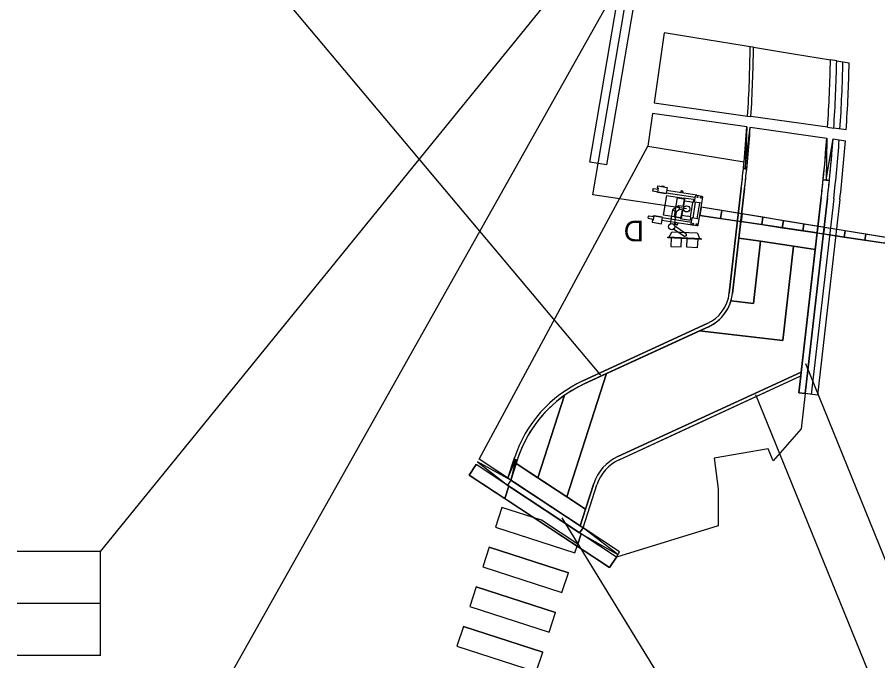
# Model space of a CAD drawing. Extents: x -728547 to -728179, y -1073068 to -1072839.
# Drawn here: x -728529.45 to -728508.81, y -1073057.23 to -1073041.79 of the extents above; entities that cross this region are included whole.
import ezdxf

# ---------------------------------------------------------------- set-up
doc = ezdxf.new("R2010")
doc.units = 0
for name, color, linetype in [('_NOR-návrh tenká', 7, 'Continuous'), ('_NOR-popis', 7, 'Continuous'), ('_NOR-VDZ', 7, 'Continuous'), ('_NOR-šraf_+-0', 7, 'Continuous'), ('_NOR-šraf_+12', 7, 'Continuous'), ('_NOR-šraf_+6', 7, 'Continuous'), ('_NOR-šraf_bezbariéra', 7, 'Continuous'), ('_NOR-šraf_chodník', 7, 'Continuous'), ('_NOR-šraf_signální pás', 7, 'Continuous'), ('_NOR-šraf_varovný pás', 7, 'Continuous'), ('_NOR-šraf_vozovka', 7, 'Continuous'), ('_NOR-šraf_zeleň', 7, 'Continuous'), ('KOS_kabelová trasa', 7, 'Continuous'), ('KOS_kabelová trasa popis', 7, 'Continuous'), ('KOS_nové prvky PZZ', 7, 'Continuous')]:
    doc.layers.add(name, color=color, linetype=linetype)

# ---------------------------------------------------------------- blocks, each defined once
blk = doc.blocks.new('Závora D')
for p, q in [((-0.7, 0.501), (-0.705, 0.472)), ((-0.599, 0.542), (-0.6, 0.536)), ((-0.539, 0.532), (-0.599, 0.542)), ((0.242, 0.325), (-0.48, 0.437)), ((0.207, 0.27), (-0.489, 0.378)), ((-0.291, -0.184), (-0.22, 0.276)), ((0.19, 0.161), (0.213, 0.305)), ((0.242, 0.325), (0.213, 0.305)), ((0.281, -0.391), (0.385, 0.279)), ((0.363, 0.306), (0.385, 0.279)), ((-0.193, 0.076), (-0.17, -0.019)), ((0.095, -0.191), (0.149, 0.155)), ((0.155, -0.223), (0.214, 0.157)), ((0.363, 0.134), (0.19, 0.161)), ((0.254, -0.239), (0.314, 0.142)), ((0.349, 0.043), (0.318, -0.155)), ((0.349, 0.043), (0.318, -0.155)), ((0.349, 0.043), (0.318, -0.155)), ((0.349, 0.043), (0.318, -0.155)), ((6.764, -1.002), (0.349, 0.043)), ((-0.337, -0.025), (-0.253, -0.076)), ((6.748, -1.108), (0.318, -0.155)), ((-0.821, -0.272), (-0.816, -0.244)), ((-0.737, -0.342), (-0.736, -0.336)), ((-0.676, -0.352), (-0.737, -0.342)), ((0.131, -0.391), (-0.591, -0.279)), ((0.114, -0.328), (-0.582, -0.22)), ((0.131, -0.391), (0.109, -0.364)), ((0.304, -0.246), (0.131, -0.219)), ((0.252, -0.41), (0.131, -0.391)), ((0.252, -0.41), (0.281, -0.391)), ((-0.069, -0.656), (-0.314, -0.489)), ((0.347, -0.72), (-0.449, -0.683)), ((6.764, -1.002), (6.748, -1.108))]:
    blk.add_line(p, q)
for points in [[(-0.807, 0.488), (-0.815, 0.434), (-0.81, 0.427), (-0.692, 0.409)], [(-0.807, 0.488), (-0.683, 0.469)], [(-0.468, 0.515), (-0.491, 0.368), (-0.694, 0.4), (-0.679, 0.497), (-0.7, 0.501), (-0.693, 0.55), (-0.468, 0.515)], [(-0.58, 0.533), (-0.54, 0.526)], [(-0.539, 0.532), (-0.54, 0.526)], [(-0.114, 0.432), (-0.127, 0.434), (-0.129, 0.428), (-0.133, 0.429), (-0.135, 0.419), (-0.138, 0.419), (-0.142, 0.396), (-0.15, 0.398), (-0.151, 0.392), (-0.152, 0.386)], [(-0.114, 0.432), (-0.101, 0.43), (-0.101, 0.423), (-0.096, 0.423), (-0.098, 0.413), (-0.094, 0.412), (-0.098, 0.389), (-0.089, 0.388), (-0.09, 0.382), (-0.091, 0.377)], [(-0.694, 0.4), (-0.716, 0.403), (-0.715, 0.412)], [(-0.494, 0.369), (-0.495, 0.361), (-0.693, 0.392), (-0.692, 0.399)], [(-0.298, -0.194), (-0.551, -0.155), (-0.477, 0.316), (-0.225, 0.277)], [(-0.225, 0.277), (-0.298, -0.194)], [(-0.221, 0.265), (-0.074, 0.242), (-0.07, 0.24), (-0.066, 0.236), (-0.063, 0.231), (-0.063, 0.226), (-0.089, 0.059)], [(-0.22, 0.276), (-0.07, 0.253), (-0.061, 0.249), (-0.055, 0.242), (-0.05, 0.235), (-0.049, 0.23), (-0.076, 0.057)], [(-0.076, 0.267), (0.168, 0.229), (0.157, 0.161), (0.149, 0.155), (0.066, 0.167), (0.067, 0.17), (-0.049, 0.188), (-0.049, 0.192), (-0.055, 0.193)], [(0.242, 0.325), (0.363, 0.306)], [(-0.063, 0.056), (-0.193, 0.076), (-0.337, -0.025), (-0.39, -0.364)], [(0.349, 0.043), (0.318, -0.155), (0.813, -0.228), (0.842, -0.038), (0.349, 0.043)], [(-0.918, -0.228), (-0.91, -0.174), (-0.903, -0.169), (-0.785, -0.187)], [(-0.604, -0.357), (-0.581, -0.21), (-0.784, -0.178), (-0.799, -0.276), (-0.821, -0.272), (-0.828, -0.322), (-0.604, -0.357)], [(-0.784, -0.178), (-0.806, -0.175), (-0.808, -0.184)], [(-0.584, -0.209), (-0.583, -0.202), (-0.781, -0.171), (-0.782, -0.179)], [(-0.072, -0.034), (-0.17, -0.019), (-0.253, -0.076), (-0.301, -0.381)], [(-0.293, -0.195), (-0.291, -0.184), (-0.144, -0.207), (-0.139, -0.206), (-0.135, -0.204), (-0.13, -0.2), (-0.128, -0.195), (-0.102, -0.03)], [(-0.293, -0.195), (-0.144, -0.218), (-0.133, -0.218), (-0.126, -0.213), (-0.119, -0.207), (-0.117, -0.203), (-0.09, -0.032)], [(-0.153, -0.231), (0.09, -0.268), (0.101, -0.2), (0.095, -0.191), (0.012, -0.178), (0.012, -0.181), (-0.103, -0.163), (-0.105, -0.167), (-0.111, -0.166)], [(0.842, -0.038), (0.813, -0.228), (1.307, -0.301), (1.336, -0.118), (0.842, -0.038)], [(1.336, -0.118), (1.307, -0.301), (1.802, -0.375), (1.829, -0.198), (1.336, -0.118)], [(1.829, -0.198), (1.802, -0.375), (2.296, -0.448), (2.323, -0.279), (1.829, -0.198)], [(-0.918, -0.228), (-0.794, -0.247)], [(-0.716, -0.339), (-0.675, -0.346)], [(-0.676, -0.352), (-0.675, -0.346)], [(-0.024, -0.588), (-0.284, -0.413)], [(-0.241, -0.385), (-0.254, -0.383), (-0.254, -0.376), (-0.258, -0.376), (-0.257, -0.366), (-0.26, -0.366), (-0.257, -0.343), (-0.265, -0.341), (-0.264, -0.335), (-0.264, -0.33)], [(-0.241, -0.385), (-0.228, -0.387), (-0.226, -0.381), (-0.222, -0.382), (-0.22, -0.372), (-0.216, -0.373), (-0.213, -0.35), (-0.204, -0.351), (-0.203, -0.345), (-0.202, -0.34)], [(0.109, -0.364), (0.131, -0.219)], [(2.323, -0.279), (2.296, -0.448), (2.791, -0.521), (2.816, -0.359), (2.323, -0.279)], [(2.816, -0.359), (2.791, -0.521), (3.286, -0.595), (3.31, -0.439), (2.816, -0.359)], [(0.317, -0.719), (0.276, -0.603), (0.256, -0.585), (-0.344, -0.557), (-0.365, -0.57), (-0.421, -0.684)], [(-0.024, -0.588), (-0.009, -0.603), (-0.006, -0.616), (-0.008, -0.631), (-0.013, -0.647), (-0.021, -0.655), (-0.032, -0.658), (-0.047, -0.661), (-0.059, -0.658), (-0.069, -0.656)], [(3.31, -0.439), (3.286, -0.595), (3.78, -0.668), (3.803, -0.52), (3.31, -0.439)], [(3.803, -0.52), (3.78, -0.668), (4.275, -0.741), (4.297, -0.6), (3.803, -0.52)], [(4.297, -0.6), (4.275, -0.741), (4.77, -0.815), (4.79, -0.68), (4.297, -0.6)], [(0.347, -0.72), (0.347, -0.734), (-0.449, -0.697), (-0.449, -0.683)], [(-0.37, -0.7), (-0.38, -0.902), (-0.129, -0.914), (-0.12, -0.712)], [(0.268, -0.73), (0.258, -0.932), (0.008, -0.92), (0.017, -0.718)], [(4.79, -0.68), (4.77, -0.815), (5.264, -0.888), (5.284, -0.761), (4.79, -0.68)], [(5.284, -0.761), (5.264, -0.888), (5.759, -0.961), (5.777, -0.841), (5.284, -0.761)], [(5.777, -0.841), (5.759, -0.961), (6.253, -1.034), (6.271, -0.922), (5.777, -0.841)], [(6.271, -0.922), (6.253, -1.034), (6.748, -1.108), (6.764, -1.002), (6.271, -0.922)]]:
    blk.add_lwpolyline(points)
for centre, radius in [((0.259, 0.284), 0.0119), ((0.342, 0.27), 0.0119), ((0, 0), 0.0742), ((-0.356, -0.429), 0.0735), ((0.16, -0.357), 0.0119), ((0.242, -0.369), 0.0119)]:
    blk.add_circle(centre, radius)

msp = doc.modelspace()

# ---------------------------------------------------------------- linework, layer by layer
at = {"layer": '_NOR-návrh tenká'}
for p, q in [((-728511.948, -1073044.42), (-728511.992, -1073045.42)), ((-728511.992, -1073045.42), (-728511.868, -1073044.431)), ((-728510.032, -1073044.689), (-728510.045, -1073045.693)), ((-728510.045, -1073045.693), (-728509.883, -1073044.71)), ((-728512.032, -1073045.416), (-728511.952, -1073045.424)), ((-728510.119, -1073045.685), (-728509.97, -1073045.701)), ((-728510.263, -1073046.965), (-728512.094, -1073046.69)), ((-728510.309, -1073047.363), (-728512.14, -1073047.088)), ((-728511.62, -1073047.166), (-728511.791, -1073048.656)), ((-728510.829, -1073047.285), (-728511.087, -1073049.542)), ((-728512.329, -1073048.595), (-728511.791, -1073048.656)), ((-728513.083, -1073049.313), (-728511.087, -1073049.542)), ((-728515.313, -1073050.341), (-728516.271, -1073053.299)), ((-728516.322, -1073050.861), (-728516.963, -1073052.841)), ((-728517.611, -1073052.893), (-728518.409, -1073052.457)), ((-728518.409, -1073052.457), (-728517.694, -1073053.019)), ((-728517.68, -1073052.848), (-728517.495, -1073052.405)), ((-728517.495, -1073052.405), (-728517.611, -1073052.893)), ((-728517.457, -1073052.418), (-728517.533, -1073052.393)), ((-728515.08, -1073054.743), (-728518.445, -1073052.523)), ((-728517.611, -1073052.893), (-728517.694, -1073053.019)), ((-728515.879, -1073054.036), (-728515.961, -1073054.161)), ((-728515.043, -1073054.677), (-728515.879, -1073054.036)), ((-728515.961, -1073054.161), (-728515.043, -1073054.677))]:
    msp.add_line(p, q, dxfattribs=at)
for points in [[(-728509.796, -1073042.832), (-728509.496, -1073042.88)], [(-728509.567, -1073044.492), (-728509.865, -1073044.45)], [(-728509.883, -1073044.71), (-728509.585, -1073044.752)], [(-728512.372, -1073048.411), (-728512.083, -1073045.892)], [(-728512.292, -1073048.42), (-728512.004, -1073045.902)], [(-728510.166, -1073046.112), (-728510.704, -1073050.803), (-728510.555, -1073050.821)], [(-728510.017, -1073046.129), (-728510.555, -1073050.821)], [(-728509.719, -1073046.164), (-728510.257, -1073050.855), (-728510.555, -1073050.821)], [(-728515.883, -1073050.516), (-728512.901, -1073049.141)], [(-728515.85, -1073050.589), (-728512.867, -1073049.214)], [(-728515.046, -1073052.332), (-728510.646, -1073050.304)], [(-728515.012, -1073052.405), (-728510.657, -1073050.397)], [(-728515.007, -1073054.612), (-728518.374, -1073052.39)], [(-728517.68, -1073052.848), (-728517.524, -1073052.364)], [(-728517.611, -1073052.893), (-728517.448, -1073052.389)], [(-728515.08, -1073054.743), (-728515.245, -1073054.993), (-728518.61, -1073052.773), (-728518.445, -1073052.523)], [(-728515.82, -1073053.596), (-728517.483, -1073052.499)], [(-728515.948, -1073053.991), (-728515.621, -1073052.98)], [(-728515.879, -1073054.036), (-728515.545, -1073053.005)]]:
    msp.add_lwpolyline(points, dxfattribs=at)
for centre, radius, start, end in [((-728544.789, -1073042.142), 32.92, 356.4854, 359.3815), ((-728544.789, -1073042.142), 33, 356.4745, 359.3607), ((-728544.789, -1073042.142), 34.85, 356.2363, 358.9053), ((-728544.789, -1073042.142), 35, 356.2181, 358.8705), ((-728544.789, -1073042.142), 35.3, 356.1822, 358.8018), ((-728544.789, -1073042.142), 32.92, 353.4578, 356.0316), ((-728544.789, -1073042.142), 33, 353.4578, 356.0218), ((-728544.789, -1073042.142), 34.85, 353.4578, 355.8078), ((-728544.789, -1073042.142), 35, 353.4578, 355.7915), ((-728544.789, -1073042.142), 35.3, 353.4578, 355.7592), ((-728513.286, -1073048.306), 0.92, 294.7505, 353.4578), ((-728513.286, -1073048.306), 1, 294.7505, 353.4578), ((-728514.594, -1073053.313), 3.08, 114.7505, 162.0512), ((-728514.594, -1073053.313), 3, 114.7505, 162.0512), ((-728514.594, -1073053.313), 1.08, 114.7505, 162.0512), ((-728514.594, -1073053.313), 1, 114.7505, 162.0512)]:
    msp.add_arc(centre, radius, start, end, dxfattribs=at)
at = {"layer": '_NOR-popis'}
for p, q in [((-728523.91, -1073040.313), (-728515.463, -1073050.376)), ((-728508.143, -1073056.009), (-728510.537, -1073050.103)), ((-728507.206, -1073061.97), (-728511.738, -1073050.849)), ((-728512.07, -1073060.816), (-728516.378, -1073053.8))]:
    msp.add_line(p, q, dxfattribs=at)
at = {"layer": '_NOR-VDZ'}
for p, q in [((-728517.824, -1073053.551), (-728517.978, -1073054.026)), ((-728516.875, -1073053.858), (-728517.824, -1073053.551)), ((-728516.007, -1073054.431), (-728516.875, -1073053.858)), ((-728517.978, -1073054.026), (-728516.075, -1073054.643)), ((-728517.978, -1073054.026), (-728516.075, -1073054.643)), ((-728518.132, -1073054.502), (-728516.229, -1073055.118)), ((-728516.075, -1073054.643), (-728516.007, -1073054.431)), ((-728518.286, -1073054.978), (-728516.384, -1073055.594)), ((-728518.44, -1073055.453), (-728516.538, -1073056.07)), ((-728518.594, -1073055.929), (-728516.692, -1073056.545)), ((-728518.748, -1073056.405), (-728516.846, -1073057.021)), ((-728518.903, -1073056.88), (-728517, -1073057.497))]:
    msp.add_line(p, q, dxfattribs=at)
for points in [[(-728509.868, -1073046.147), (-728510.406, -1073050.838)], [(-728518.286, -1073054.978), (-728516.384, -1073055.594), (-728516.229, -1073055.118), (-728518.132, -1073054.502), (-728518.286, -1073054.978)], [(-728518.594, -1073055.929), (-728516.692, -1073056.545), (-728516.538, -1073056.07), (-728518.44, -1073055.453), (-728518.594, -1073055.929), (-728518.594, -1073055.929)], [(-728518.903, -1073056.88), (-728517, -1073057.497), (-728516.846, -1073057.021), (-728518.748, -1073056.405), (-728518.903, -1073056.88)]]:
    msp.add_lwpolyline(points, dxfattribs=at)
for start, end in [(356.2001, 358.836), (353.4578, 355.7753)]:
    msp.add_arc((-728544.789, -1073042.142), 35.15, start, end, dxfattribs=at)
at = {"layer": '_NOR-šraf_+-0'}
for p, q in [((-728511.791, -1073042.51), (-728511.871, -1073042.497)), ((-728509.796, -1073042.832), (-728509.945, -1073042.808)), ((-728511.931, -1073044.16), (-728511.851, -1073044.171)), ((-728510.014, -1073044.429), (-728509.865, -1073044.45))]:
    msp.add_line(p, q, dxfattribs=at)
for points in [[(-728515.012, -1073052.405), (-728510.657, -1073050.397), (-728510.646, -1073050.304), (-728515.046, -1073052.332)], [(-728515.621, -1073052.98), (-728515.82, -1073053.596), (-728515.948, -1073053.991), (-728515.879, -1073054.036)], [(-728515.879, -1073054.036), (-728515.545, -1073053.005)]]:
    msp.add_lwpolyline(points, dxfattribs=at)
for centre, radius, start, end in [((-728544.789, -1073042.142), 32.92, 356.4854, 359.3815), ((-728544.789, -1073042.142), 33, 356.4745, 359.3607), ((-728544.789, -1073042.142), 34.85, 356.2363, 358.9053), ((-728544.789, -1073042.142), 35, 356.2181, 358.8705), ((-728514.594, -1073053.313), 1.08, 114.7505, 162.0512), ((-728514.594, -1073053.313), 1, 114.7505, 162.0512)]:
    msp.add_arc(centre, radius, start, end, dxfattribs=at)
at = {"layer": '_NOR-šraf_+12'}
for p, q in [((-728510.016, -1073045.702), (-728510.12, -1073045.691)), ((-728510.119, -1073045.685), (-728510.013, -1073045.696)), ((-728510.016, -1073045.702), (-728510.013, -1073045.696)), ((-728510.013, -1073045.696), (-728510.016, -1073045.702)), ((-728509.971, -1073045.706), (-728510.016, -1073045.702)), ((-728510.013, -1073045.696), (-728509.97, -1073045.701))]:
    msp.add_line(p, q, dxfattribs=at)
for points in [[(-728510.12, -1073045.691), (-728510.045, -1073045.699), (-728509.971, -1073045.706)], [(-728510.017, -1073046.129), (-728510.555, -1073050.821), (-728510.704, -1073050.803), (-728510.657, -1073050.397), (-728510.646, -1073050.304)], [(-728510.646, -1073050.304), (-728510.166, -1073046.112)]]:
    msp.add_lwpolyline(points, dxfattribs=at)
for centre, radius, start, end in [((-728544.789, -1073042.142), 34.85, 353.4578, 354.1544), ((-728544.789, -1073042.142), 34.85, 354.1544, 354.1637), ((-728544.789, -1073042.142), 35, 353.4578, 354.1544), ((-728544.784, -1073042.142), 34.996, 354.1544, 354.1637)]:
    msp.add_arc(centre, radius, start, end, dxfattribs=at)
at = {"layer": '_NOR-šraf_+6'}
for p, q in [((-728512.032, -1073045.416), (-728511.952, -1073045.424)), ((-728511.953, -1073045.428), (-728512.032, -1073045.42))]:
    msp.add_line(p, q, dxfattribs=at)
for points in [[(-728512.032, -1073045.42), (-728511.993, -1073045.424), (-728511.953, -1073045.428)], [(-728512.372, -1073048.411), (-728512.083, -1073045.892)], [(-728512.004, -1073045.902), (-728512.292, -1073048.42)], [(-728515.883, -1073050.516), (-728512.901, -1073049.141)], [(-728512.867, -1073049.214), (-728515.313, -1073050.341), (-728515.85, -1073050.589)], [(-728517.533, -1073052.393), (-728517.524, -1073052.364)], [(-728517.448, -1073052.389), (-728517.457, -1073052.418), (-728517.495, -1073052.405), (-728517.533, -1073052.393)]]:
    msp.add_lwpolyline(points, dxfattribs=at)
for centre, radius, start, end in [((-728544.789, -1073042.142), 32.92, 353.4578, 354.2855), ((-728544.808, -1073042.14), 32.94, 354.2855, 354.2911), ((-728544.789, -1073042.142), 33, 353.4578, 354.2855), ((-728544.752, -1073042.145), 32.963, 354.2855, 354.2911), ((-728513.286, -1073048.306), 0.92, 294.7505, 353.4578), ((-728513.286, -1073048.306), 1, 294.7505, 353.4578), ((-728514.594, -1073053.313), 3.08, 114.7505, 162.0512), ((-728514.594, -1073053.313), 3, 114.7505, 125.1813), ((-728514.594, -1073053.313), 3, 125.1813, 162.0512)]:
    msp.add_arc(centre, radius, start, end, dxfattribs=at)
at = {"layer": '_NOR-šraf_bezbariéra'}
msp.add_lwpolyline([(-728515.961, -1073054.161), (-728515.879, -1073054.036), (-728515.948, -1073053.991), (-728517.611, -1073052.893), (-728517.694, -1073053.019), (-728517.659, -1073053.042), (-728515.961, -1073054.161), (-728515.961, -1073054.161)], dxfattribs=at)
at = {"layer": '_NOR-šraf_chodník'}
for p, q in [((-728510.014, -1073044.429), (-728511.851, -1073044.171)), ((-728511.868, -1073044.431), (-728510.032, -1073044.689)), ((-728512.329, -1073048.595), (-728511.791, -1073048.656)), ((-728516.963, -1073052.841), (-728516.322, -1073050.861)), ((-728515.82, -1073053.596), (-728515.621, -1073052.98))]:
    msp.add_line(p, q, dxfattribs=at)
for points in [[(-728511.791, -1073042.51), (-728510.831, -1073042.665), (-728509.945, -1073042.808)], [(-728510.166, -1073046.112), (-728510.263, -1073046.965), (-728512.094, -1073046.69), (-728512.004, -1073045.902)], [(-728511.791, -1073048.656), (-728511.62, -1073047.166), (-728512.14, -1073047.088), (-728512.292, -1073048.42)], [(-728515.046, -1073052.332), (-728510.646, -1073050.304), (-728510.309, -1073047.363), (-728510.829, -1073047.285), (-728511.087, -1073049.542), (-728513.083, -1073049.313), (-728515.313, -1073050.341), (-728516.271, -1073053.299), (-728515.82, -1073053.596)], [(-728517.448, -1073052.389), (-728517.457, -1073052.418), (-728517.483, -1073052.499), (-728516.963, -1073052.841)]]:
    msp.add_lwpolyline(points, dxfattribs=at)
for centre, radius, start, end in [((-728544.789, -1073042.142), 33, 356.4745, 359.3607), ((-728544.789, -1073042.142), 34.85, 356.2363, 358.9053), ((-728544.789, -1073042.142), 33, 354.2855, 356.0218), ((-728544.789, -1073042.142), 34.85, 354.1544, 355.8078), ((-728544.789, -1073042.142), 33, 353.4578, 354.2855), ((-728544.789, -1073042.142), 34.85, 353.4578, 354.1544), ((-728513.286, -1073048.306), 1, 343.2051, 353.4578), ((-728514.594, -1073053.313), 3, 125.1813, 162.0512), ((-728514.594, -1073053.313), 1.08, 114.7505, 162.0512)]:
    msp.add_arc(centre, radius, start, end, dxfattribs=at)
at = {"layer": '_NOR-šraf_signální pás'}
for points in [[(-728511.087, -1073049.542), (-728510.829, -1073047.285), (-728511.62, -1073047.166), (-728511.791, -1073048.656), (-728512.329, -1073048.595)], [(-728512.867, -1073049.214), (-728513.083, -1073049.313), (-728511.087, -1073049.542)], [(-728516.271, -1073053.299), (-728515.313, -1073050.341), (-728515.85, -1073050.589)], [(-728516.322, -1073050.861), (-728516.963, -1073052.841), (-728516.271, -1073053.299), (-728516.271, -1073053.299)]]:
    msp.add_lwpolyline(points, dxfattribs=at)
for centre, radius, start, end in [((-728513.286, -1073048.306), 1, 294.7505, 343.2051), ((-728514.594, -1073053.313), 3, 114.7505, 125.1813)]:
    msp.add_arc(centre, radius, start, end, dxfattribs=at)
at = {"layer": '_NOR-šraf_varovný pás'}
for points in [[(-728511.62, -1073047.166), (-728510.829, -1073047.285), (-728510.309, -1073047.363), (-728510.263, -1073046.965), (-728512.094, -1073046.69), (-728512.14, -1073047.088), (-728511.62, -1073047.166)], [(-728517.611, -1073052.893), (-728517.611, -1073052.893), (-728515.948, -1073053.991), (-728515.82, -1073053.596), (-728516.271, -1073053.299), (-728516.963, -1073052.841), (-728517.483, -1073052.499), (-728517.611, -1073052.893), (-728517.611, -1073052.893)]]:
    msp.add_lwpolyline(points, dxfattribs=at)
at = {"layer": '_NOR-šraf_vozovka'}
for p, q in [((-728509.796, -1073042.832), (-728509.496, -1073042.88)), ((-728509.567, -1073044.492), (-728509.865, -1073044.45)), ((-728509.883, -1073044.71), (-728509.585, -1073044.752)), ((-728510.555, -1073050.821), (-728510.017, -1073046.129)), ((-728515.927, -1073054.184), (-728516.023, -1073054.48)), ((-728516.023, -1073054.48), (-728515.927, -1073054.184)), ((-728516.023, -1073054.48), (-728515.245, -1073054.993))]:
    msp.add_line(p, q, dxfattribs=at)
for points in [[(-728509.719, -1073046.164), (-728510.257, -1073050.855), (-728510.555, -1073050.821)], [(-728517.755, -1073053.338), (-728517.659, -1073053.042), (-728518.445, -1073052.523), (-728518.61, -1073052.773), (-728517.755, -1073053.338)], [(-728515.927, -1073054.184), (-728515.961, -1073054.161), (-728517.659, -1073053.042), (-728517.755, -1073053.338), (-728516.023, -1073054.48)], [(-728515.245, -1073054.993), (-728515.08, -1073054.743), (-728515.927, -1073054.184)]]:
    msp.add_lwpolyline(points, dxfattribs=at)
for radius, start, end in [(35, 356.2181, 358.8705), (35.3, 356.1822, 358.8018), (35, 354.1544, 355.7915), (35.3, 353.4578, 355.7592), (35, 353.4578, 354.1544)]:
    msp.add_arc((-728544.789, -1073042.142), radius, start, end, dxfattribs=at)
at = {"layer": '_NOR-šraf_zeleň'}
for p, q in [((-728514.174, -1073043.844), (-728511.931, -1073044.16)), ((-728511.948, -1073044.42), (-728514.212, -1073044.102)), ((-728512.083, -1073045.892), (-728512.372, -1073048.411)), ((-728512.901, -1073049.141), (-728515.883, -1073050.516)), ((-728515.879, -1073054.036), (-728515.545, -1073053.005))]:
    msp.add_line(p, q, dxfattribs=at)
for points in [[(-728511.871, -1073042.497), (-728512.015, -1073042.474), (-728513.198, -1073042.283), (-728513.93, -1073042.165), (-728514.174, -1073043.844)], [(-728514.212, -1073044.102), (-728514.327, -1073044.886), (-728512.017, -1073045.259)], [(-728518.374, -1073052.39), (-728514.327, -1073044.886), (-728512.017, -1073045.259)], [(-728515.012, -1073052.405), (-728513.339, -1073051.634), (-728510.657, -1073050.397), (-728510.704, -1073050.803), (-728510.555, -1073050.821), (-728510.651, -1073051.661), (-728511.32, -1073052.432), (-728511.438, -1073052.141), (-728512.732, -1073052.372), (-728512.635, -1073053.106), (-728512.638, -1073053.993), (-728515.08, -1073054.743), (-728515.007, -1073054.612), (-728515.879, -1073054.036)], [(-728517.524, -1073052.364), (-728517.533, -1073052.393), (-728517.68, -1073052.848), (-728518.374, -1073052.39)]]:
    msp.add_lwpolyline(points, dxfattribs=at)
for centre, radius, start, end in [((-728544.789, -1073042.142), 32.92, 356.4854, 359.3815), ((-728544.789, -1073042.142), 32.92, 354.5662, 356.0316), ((-728544.789, -1073042.142), 32.92, 353.4578, 354.2855), ((-728544.789, -1073042.142), 32.92, 354.2855, 354.5662), ((-728513.286, -1073048.306), 0.92, 294.7505, 353.4578), ((-728514.594, -1073053.313), 3.08, 114.7505, 162.0512), ((-728514.594, -1073053.313), 1, 114.7505, 162.0512)]:
    msp.add_arc(centre, radius, start, end, dxfattribs=at)
at = {"layer": 'KOS_kabelová trasa'}
for points in [[(-728513.395, -1073046.387), (-728515.647, -1073046.052), (-728513.917, -1073035.879)], [(-728515.318, -1073045.332), (-728515.712, -1073045.265), (-728514.228, -1073036.535), (-728513.834, -1073036.602), (-728515.318, -1073045.332)]]:
    msp.add_lwpolyline(points, dxfattribs=at)
at = {"layer": 'KOS_kabelová trasa popis'}
for p, q in [((-728527.449, -1073054.604), (-728514.328, -1073038.456)), ((-728514.97, -1073040.9), (-728525.475, -1073059.597)), ((-728527.449, -1073054.604), (-728529.449, -1073054.604)), ((-728527.449, -1073057.104), (-728527.449, -1073054.604)), ((-728527.449, -1073055.854), (-728529.449, -1073055.854)), ((-728527.449, -1073057.104), (-728529.449, -1073057.104))]:
    msp.add_line(p, q, dxfattribs=at)

# ---------------------------------------------------------------- block references
at = {"layer": 'KOS_nové prvky PZZ', "rotation": -0.11438322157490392}
msp.add_blockref('Závora D', (-728513.395, -1073046.387), dxfattribs=at)

# ---------------------------------------------------------------- texts
at = {"layer": 'KOS_nové prvky PZZ'}
msp.add_text('D', height=0.5, rotation=180, dxfattribs=at).set_placement((-728514.419, -1073046.67))

doc.saveas('drawing.dxf')
